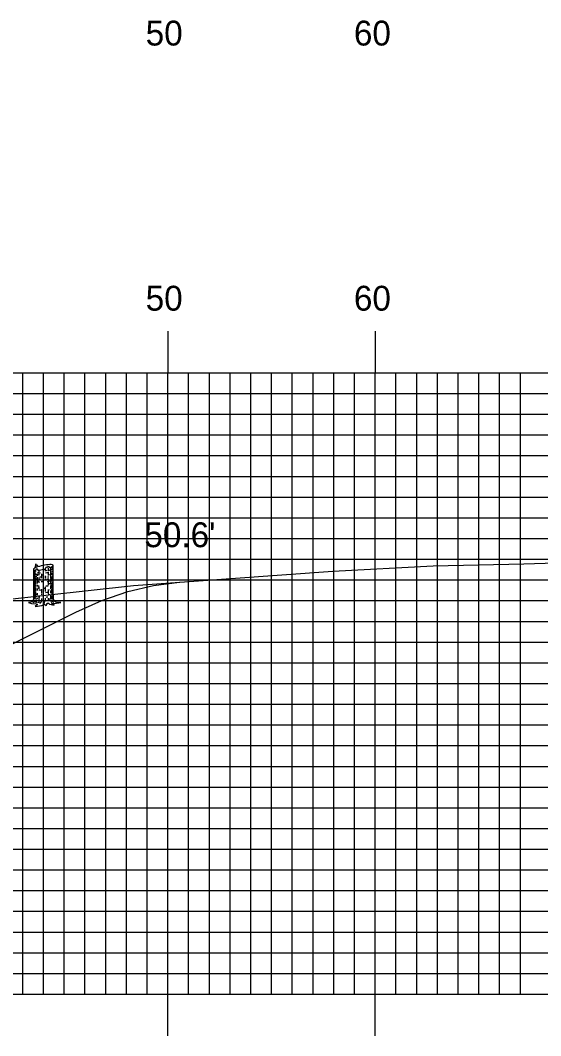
# Model space of a CAD drawing. Extents: x 1823966 to 1824309, y 442591 to 442811.
# Drawn here: x 1824174.71 to 1824199.8, y 442694.58 to 442743.61 of the extents above; entities that cross this region are included whole.
import ezdxf

# ---------------------------------------------------------------- set-up
doc = ezdxf.new("R2010")
doc.units = 0
for name, color, linetype in [('D_Roadway_Centerline', 7, 'Continuous'), ('D_Roadway_SlopeLines', 7, 'Continuous'), ('D_Text_Standard', 7, 'Continuous'), ('H_V ANNOTATION', 7, 'Continuous'), ('MAJOR', 7, 'Continuous'), ('MINOR', 7, 'Continuous'), ('S_Roadway_Centerline', 7, 'Continuous'), ('S_Trees_Decid_NonPay', 7, 'Continuous')]:
    doc.layers.add(name, color=color, linetype=linetype)

msp = doc.modelspace()

# ---------------------------------------------------------------- linework, layer by layer
at = {"layer": 'D_Roadway_Centerline'}
msp.add_lwpolyline([(1824101.648, 442710.342), (1824108.91, 442712.157), (1824111.822, 442712.885), (1824119.822, 442713.205), (1824131.822, 442713.445), (1824143.822, 442713.205), (1824151.822, 442712.885), (1824161.996, 442710.342), (1824165.996, 442709.342), (1824177.386, 442715.037), (1824178.636, 442715.596), (1824179.886, 442716.022), (1824181.136, 442716.317), (1824182.386, 442716.479)], dxfattribs=at)
at = {"layer": 'D_Roadway_SlopeLines'}
msp.add_lwpolyline([(1824165.996, 442709.342), (1824177.386, 442715.037), (1824178.636, 442715.596), (1824179.886, 442716.022), (1824181.136, 442716.317), (1824182.386, 442716.479)], dxfattribs=at)
at = {"layer": 'MAJOR'}
for p, q in [((1824181.822, 442728.592), (1824181.822, 442726.588)), ((1824191.822, 442728.592), (1824191.822, 442726.588)), ((1823991.822, 442726.588), (1824271.822, 442726.588)), ((1823991.822, 442726.588), (1824271.822, 442726.588)), ((1824181.822, 442696.588), (1824181.822, 442726.588)), ((1824191.822, 442696.588), (1824191.822, 442726.588)), ((1823991.822, 442721.588), (1824271.822, 442721.588)), ((1823991.822, 442716.588), (1824271.822, 442716.588)), ((1823991.822, 442711.588), (1824271.822, 442711.588)), ((1823991.822, 442706.588), (1824271.822, 442706.588)), ((1823991.822, 442701.588), (1824271.822, 442701.588)), ((1823991.822, 442696.588), (1824271.822, 442696.588)), ((1823991.822, 442696.588), (1824271.822, 442696.588)), ((1824181.822, 442694.584), (1824181.822, 442696.588)), ((1824191.822, 442694.584), (1824191.822, 442696.588))]:
    msp.add_line(p, q, dxfattribs=at)
at = {"layer": 'MINOR'}
for p, q in [((1824174.822, 442696.588), (1824174.822, 442726.588)), ((1824175.822, 442696.588), (1824175.822, 442726.588)), ((1824176.822, 442696.588), (1824176.822, 442726.588)), ((1824177.822, 442696.588), (1824177.822, 442726.588)), ((1824178.822, 442696.588), (1824178.822, 442726.588)), ((1824179.822, 442696.588), (1824179.822, 442726.588)), ((1824180.822, 442696.588), (1824180.822, 442726.588)), ((1824182.822, 442696.588), (1824182.822, 442726.588)), ((1824183.822, 442696.588), (1824183.822, 442726.588)), ((1824184.822, 442696.588), (1824184.822, 442726.588)), ((1824185.822, 442696.588), (1824185.822, 442726.588)), ((1824186.822, 442696.588), (1824186.822, 442726.588)), ((1824187.822, 442696.588), (1824187.822, 442726.588)), ((1824188.822, 442696.588), (1824188.822, 442726.588)), ((1824189.822, 442696.588), (1824189.822, 442726.588)), ((1824190.822, 442696.588), (1824190.822, 442726.588)), ((1824192.822, 442696.588), (1824192.822, 442726.588)), ((1824193.822, 442696.588), (1824193.822, 442726.588)), ((1824194.822, 442696.588), (1824194.822, 442726.588)), ((1824195.822, 442696.588), (1824195.822, 442726.588)), ((1824196.822, 442696.588), (1824196.822, 442726.588)), ((1824197.822, 442696.588), (1824197.822, 442726.588)), ((1824198.822, 442696.588), (1824198.822, 442726.588)), ((1823991.822, 442725.588), (1824271.822, 442725.588)), ((1823991.822, 442724.588), (1824271.822, 442724.588)), ((1823991.822, 442723.588), (1824271.822, 442723.588)), ((1823991.822, 442722.588), (1824271.822, 442722.588)), ((1823991.822, 442720.588), (1824271.822, 442720.588)), ((1823991.822, 442719.588), (1824271.822, 442719.588)), ((1823991.822, 442718.588), (1824271.822, 442718.588)), ((1823991.822, 442717.588), (1824271.822, 442717.588)), ((1823991.822, 442715.588), (1824271.822, 442715.588)), ((1823991.822, 442714.588), (1824271.822, 442714.588)), ((1823991.822, 442713.588), (1824271.822, 442713.588)), ((1823991.822, 442712.588), (1824271.822, 442712.588)), ((1823991.822, 442710.588), (1824271.822, 442710.588)), ((1823991.822, 442709.588), (1824271.822, 442709.588)), ((1823991.822, 442708.588), (1824271.822, 442708.588)), ((1823991.822, 442707.588), (1824271.822, 442707.588)), ((1823991.822, 442705.588), (1824271.822, 442705.588)), ((1823991.822, 442704.588), (1824271.822, 442704.588)), ((1823991.822, 442703.588), (1824271.822, 442703.588)), ((1823991.822, 442702.588), (1824271.822, 442702.588)), ((1823991.822, 442700.588), (1824271.822, 442700.588)), ((1823991.822, 442699.588), (1824271.822, 442699.588)), ((1823991.822, 442698.588), (1824271.822, 442698.588)), ((1823991.822, 442697.588), (1824271.822, 442697.588))]:
    msp.add_line(p, q, dxfattribs=at)
at = {"layer": 'S_Roadway_Centerline'}
msp.add_lwpolyline([(1824143.98, 442712.654), (1824145.907, 442712.678), (1824147.989, 442712.271), (1824148.362, 442712.203), (1824148.8, 442712.127), (1824152.854, 442711.284), (1824152.982, 442711.332), (1824155.841, 442711.355), (1824155.942, 442711.352), (1824156.136, 442711.464), (1824156.836, 442711.769), (1824157.71, 442712.162), (1824159.394, 442712.816), (1824164.55, 442714.059), (1824169.771, 442715.212), (1824170.867, 442715.316), (1824171.695, 442715.382), (1824180.171, 442716.318), (1824189.783, 442717.016), (1824194.617, 442717.262), (1824198.985, 442717.368), (1824210.288, 442717.724)], dxfattribs=at)
at = {"layer": 'S_Trees_Decid_NonPay'}
for p, q in [((1824176.046, 442717.161), (1824176.046, 442717.013)), ((1824176.164, 442717.144), (1824176.164, 442716.844)), ((1824176.233, 442717.231), (1824176.233, 442717.136)), ((1824175.374, 442716.988), (1824175.374, 442716.906)), ((1824175.374, 442716.836), (1824175.374, 442716.706)), ((1824175.374, 442716.684), (1824175.374, 442716.502)), ((1824175.401, 442717.058), (1824175.401, 442716.84)), ((1824175.401, 442716.771), (1824175.401, 442716.619)), ((1824175.444, 442717.053), (1824175.444, 442717.001)), ((1824175.444, 442716.898), (1824175.444, 442716.815)), ((1824175.444, 442716.78), (1824175.444, 442716.706)), ((1824175.444, 442716.679), (1824175.444, 442716.619)), ((1824175.515, 442716.879), (1824175.515, 442716.793)), ((1824175.515, 442716.722), (1824175.515, 442716.601)), ((1824175.601, 442717.063), (1824175.601, 442716.984)), ((1824175.601, 442716.898), (1824175.601, 442716.813)), ((1824175.601, 442716.702), (1824175.601, 442716.601)), ((1824175.719, 442716.879), (1824175.719, 442716.679)), ((1824175.899, 442717.115), (1824175.899, 442717.009)), ((1824175.899, 442716.78), (1824175.899, 442716.694)), ((1824175.899, 442716.659), (1824175.899, 442716.589)), ((1824176.046, 442716.965), (1824176.046, 442716.797)), ((1824176.164, 442716.815), (1824176.164, 442716.684)), ((1824176.164, 442716.65), (1824176.164, 442716.369)), ((1824176.233, 442716.91), (1824176.233, 442716.827)), ((1824176.233, 442716.758), (1824176.233, 442716.507)), ((1824175.374, 442716.455), (1824175.374, 442716.208)), ((1824175.374, 442716.189), (1824175.374, 442716.095)), ((1824175.401, 442716.514), (1824175.401, 442716.436)), ((1824175.401, 442716.409), (1824175.401, 442716.303)), ((1824175.401, 442716.268), (1824175.401, 442716.167)), ((1824175.444, 442716.566), (1824175.444, 442716.385)), ((1824175.444, 442716.354), (1824175.444, 442716.272)), ((1824175.444, 442716.218), (1824175.444, 442716.047)), ((1824175.515, 442716.526), (1824175.515, 442716.411)), ((1824175.515, 442716.35), (1824175.515, 442716.268)), ((1824175.515, 442716.181), (1824175.515, 442716.084)), ((1824175.601, 442716.516), (1824175.601, 442716.44)), ((1824175.601, 442716.255), (1824175.601, 442716.158)), ((1824175.899, 442716.255), (1824175.899, 442716.033)), ((1824176.046, 442716.49), (1824176.046, 442716.342)), ((1824176.164, 442716.299), (1824176.164, 442716.154)), ((1824176.233, 442716.424), (1824176.233, 442716.194)), ((1824175.372, 442716.041), (1824175.374, 442715.782)), ((1824175.374, 442715.743), (1824175.374, 442715.669)), ((1824175.401, 442716.141), (1824175.401, 442715.959)), ((1824175.401, 442715.856), (1824175.401, 442715.664)), ((1824175.444, 442716.014), (1824175.444, 442715.734)), ((1824175.444, 442715.682), (1824175.444, 442715.656)), ((1824175.515, 442715.955), (1824175.515, 442715.856)), ((1824175.515, 442715.726), (1824175.515, 442715.668)), ((1824175.601, 442715.833), (1824175.601, 442715.609)), ((1824175.719, 442716.142), (1824175.719, 442715.955)), ((1824175.719, 442715.924), (1824175.719, 442715.871)), ((1824175.719, 442715.695), (1824175.719, 442715.604)), ((1824175.899, 442715.699), (1824175.899, 442715.633)), ((1824176.046, 442716.072), (1824176.046, 442715.919)), ((1824176.046, 442715.707), (1824176.046, 442715.629)), ((1824176.164, 442716.084), (1824176.164, 442715.942)), ((1824176.164, 442715.841), (1824176.164, 442715.66)), ((1824176.233, 442716.123), (1824176.233, 442715.963)), ((1824176.233, 442715.946), (1824176.233, 442715.841)), ((1824176.233, 442715.804), (1824176.233, 442715.68)), ((1824175.321, 442715.495), (1824175.389, 442715.526)), ((1824175.403, 442715.617), (1824175.368, 442715.566)), ((1824175.859, 442715.413), (1824175.893, 442715.559)), ((1824176.165, 442715.6), (1824176.206, 442715.504))]:
    msp.add_line(p, q, dxfattribs=at)
for points in [[(1824175.333, 442717.095), (1824175.333, 442715.683), (1824175.311, 442715.535), (1824175.107, 442715.491), (1824175.247, 442715.456), (1824175.466, 442715.438), (1824175.535, 442715.394), (1824175.414, 442715.306), (1824175.745, 442715.349), (1824175.859, 442715.413), (1824175.951, 442715.353), (1824176.007, 442715.432), (1824175.998, 442715.469), (1824176.06, 442715.47), (1824176.112, 442715.413), (1824176.344, 442715.362), (1824176.217, 442715.45), (1824176.349, 442715.452), (1824176.657, 442715.49), (1824176.418, 442715.52), (1824176.34, 442715.578), (1824176.302, 442715.699), (1824176.284, 442716.053), (1824176.284, 442717.287)], [(1824175.428, 442717.176), (1824175.432, 442717.27), (1824175.447, 442717.243), (1824175.447, 442717.365), (1824175.468, 442717.301), (1824175.482, 442717.334), (1824175.498, 442717.278), (1824175.515, 442717.295), (1824175.533, 442717.287), (1824175.552, 442717.22)], [(1824175.45, 442717.052), (1824175.468, 442717.114), (1824175.49, 442717.102), (1824175.521, 442717.136), (1824175.554, 442717.058)], [(1824175.92, 442717.121), (1824175.929, 442717.188), (1824175.953, 442717.192), (1824175.962, 442717.227), (1824175.992, 442717.213), (1824176.007, 442717.227), (1824176.031, 442717.204), (1824176.054, 442717.213), (1824176.067, 442717.262), (1824176.075, 442717.219), (1824176.105, 442717.227), (1824176.109, 442717.176)], [(1824175.372, 442715.543), (1824175.451, 442715.526), (1824175.468, 442715.483)], [(1824175.451, 442715.526), (1824175.494, 442715.561), (1824175.502, 442715.609)], [(1824175.599, 442715.561), (1824175.593, 442715.491), (1824175.529, 442715.479)], [(1824175.71, 442715.555), (1824175.71, 442715.518), (1824175.659, 442715.488), (1824175.642, 442715.438)], [(1824176.235, 442715.638), (1824176.244, 442715.561), (1824176.322, 442715.512)]]:
    msp.add_lwpolyline(points, dxfattribs=at)
for centre, radius, start, end in [((1824175.567, 442716.886), 0.322, 109.7098, 131.8277), ((1824176.304, 442714.828), 2.507, 101.8277, 109.7098), ((1824176.304, 442714.828), 2.507, 93.9457, 101.8277), ((1824175.314, 442719.554), 2.507, 288.4719, 289.7098), ((1824176.153, 442717.008), 0.322, 71.8277, 93.9457), ((1824176.051, 442717.496), 0.322, 289.7098, 311.8277), ((1824176.224, 442717.225), 0.0935, 60.604, 71.8277), ((1824176.203, 442717.326), 0.0935, 311.8277, 323.0514), ((1824176.254, 442717.278), 0.0336, 41.8277, 60.604), ((1824176.251, 442717.29), 0.0336, 323.0514, 341.8277), ((1824176.261, 442717.284), 0.0237, 27.8832, 41.8277), ((1824176.266, 442717.287), 0.0179, 11.8277, 27.8832), ((1824176.26, 442717.141), 0.0252, 330, 343.9485), ((1824176.26, 442717.287), 0.0237, 341.8277, 355.7722), ((1824176.266, 442717.287), 0.0179, 355.7722, 11.8277), ((1824176.266, 442717.139), 0.0191, 0, 16.0515), ((1824176.266, 442717.139), 0.0191, 343.9485, 0), ((1824175.357, 442717.095), 0.0237, 161.8277, 175.7722), ((1824175.351, 442717.095), 0.0179, 175.7722, 191.8277), ((1824175.351, 442717.095), 0.0179, 191.8277, 207.8832), ((1824175.353, 442717.026), 0.0191, 173.8872, 180), ((1824175.353, 442717.026), 0.0191, 180, 196.0515), ((1824175.353, 442716.925), 0.0191, 173.8872, 180), ((1824175.353, 442716.925), 0.0191, 180, 196.0515), ((1824175.353, 442716.822), 0.0191, 173.8872, 180), ((1824175.353, 442716.822), 0.0191, 180, 196.0515), ((1824175.353, 442716.717), 0.0191, 173.8872, 180), ((1824175.353, 442716.717), 0.0191, 180, 196.0515), ((1824175.366, 442717.092), 0.0336, 143.0514, 161.8277), ((1824175.356, 442717.098), 0.0237, 207.8832, 221.8277), ((1824175.359, 442717.028), 0.0252, 196.0515, 210), ((1824175.359, 442716.927), 0.0252, 196.0515, 210), ((1824175.359, 442716.719), 0.0252, 196.0515, 210), ((1824175.368, 442717.033), 0.0356, 210, 228.7494), ((1824175.368, 442716.932), 0.0356, 210, 228.7494), ((1824175.368, 442716.724), 0.0356, 210, 228.7494), ((1824175.364, 442717.105), 0.0336, 221.8277, 240.604), ((1824175.414, 442717.056), 0.0935, 131.8277, 143.0514), ((1824175.409, 442717.08), 0.0984, 228.7494, 240), ((1824175.409, 442716.979), 0.0984, 228.7494, 240), ((1824175.409, 442716.771), 0.0984, 228.7494, 240), ((1824175.393, 442717.157), 0.0935, 240.604, 251.8277), ((1824175.523, 442717.277), 0.326, 240, 248.0494), ((1824175.523, 442717.177), 0.326, 240, 248.0494), ((1824175.523, 442716.969), 0.326, 240, 248.0494), ((1824175.464, 442717.374), 0.322, 251.8277, 267.5521), ((1824175.523, 442717.074), 0.326, 255.9618, 261.8968), ((1824175.523, 442716.969), 0.326, 255.9618, 261.8968), ((1824175.523, 442717.177), 0.326, 260.9146, 261.8968), ((1824175.81, 442719.187), 2.356, 261.8968, 264.9353), ((1824175.81, 442719.084), 2.356, 261.8968, 262.6162), ((1824175.81, 442718.979), 2.356, 261.8968, 262.8132), ((1824175.81, 442719.288), 2.356, 263.2266, 266.8519), ((1824175.314, 442719.554), 2.507, 275.4987, 281.8277), ((1824175.81, 442719.084), 2.356, 266.0259, 267.8019), ((1824175.81, 442719.187), 2.356, 267.8019, 269.1881), ((1824175.314, 442719.554), 2.507, 281.8277, 284.0013), ((1824175.81, 442719.401), 2.356, 272.1614, 274.76), ((1824175.81, 442719.084), 2.356, 272.1614, 273.4964), ((1824175.81, 442719.288), 2.356, 272.6327, 275.758), ((1824175.81, 442719.084), 2.356, 275.0054, 276.6587), ((1824175.81, 442719.401), 2.356, 276.7201, 278.1032), ((1824175.81, 442719.187), 2.356, 277.4481, 278.1032), ((1824176.096, 442717.391), 0.326, 278.1032, 282.1964), ((1824176.096, 442717.177), 0.326, 278.1032, 289.5833), ((1824176.096, 442717.277), 0.326, 282.1964, 299.0901), ((1824176.096, 442717.074), 0.326, 282.1964, 288.3169), ((1824176.096, 442716.969), 0.326, 282.1964, 294.8455), ((1824176.096, 442717.391), 0.326, 291.6757, 300), ((1824176.096, 442717.177), 0.326, 296.4281, 300), ((1824176.096, 442717.074), 0.326, 296.757, 300), ((1824176.21, 442717.194), 0.0984, 300, 311.2506), ((1824176.21, 442716.979), 0.0984, 300, 311.2506), ((1824176.21, 442716.876), 0.0984, 300, 311.2506), ((1824176.251, 442717.146), 0.0356, 311.2506, 330), ((1824176.251, 442716.932), 0.0356, 311.2506, 330), ((1824176.251, 442716.829), 0.0356, 311.2506, 330), ((1824176.26, 442716.927), 0.0252, 330, 343.9485), ((1824176.26, 442716.824), 0.0252, 330, 343.9485), ((1824176.266, 442716.925), 0.0191, 0, 16.0515), ((1824176.266, 442716.925), 0.0191, 343.9485, 0), ((1824176.266, 442716.822), 0.0191, 0, 16.0515), ((1824176.266, 442716.822), 0.0191, 343.9485, 0), ((1824175.352, 442716.488), 0.0191, 173.8872, 180), ((1824175.352, 442716.488), 0.0191, 180, 196.0515), ((1824175.353, 442716.602), 0.0191, 173.8872, 180), ((1824175.353, 442716.602), 0.0191, 180, 196.0515), ((1824175.358, 442716.49), 0.0252, 196.0515, 210), ((1824175.353, 442716.283), 0.0191, 173.8872, 180), ((1824175.353, 442716.283), 0.0191, 180, 196.0515), ((1824175.353, 442716.192), 0.0191, 173.8872, 180), ((1824175.359, 442716.604), 0.0252, 196.0515, 210), ((1824175.359, 442716.285), 0.0252, 196.0515, 210), ((1824175.367, 442716.495), 0.0356, 210, 228.7494), ((1824175.356, 442716.388), 0.0191, 173.8872, 180), ((1824175.356, 442716.388), 0.0191, 180, 196.0515), ((1824175.368, 442716.609), 0.0356, 210, 228.7494), ((1824175.361, 442716.389), 0.0252, 196.0515, 210), ((1824175.368, 442716.29), 0.0356, 210, 228.7494), ((1824175.37, 442716.395), 0.0356, 210, 228.7494), ((1824175.409, 442716.542), 0.0984, 228.7494, 240), ((1824175.409, 442716.656), 0.0984, 228.7494, 240), ((1824175.409, 442716.337), 0.0984, 228.7494, 240), ((1824175.412, 442716.442), 0.0984, 228.7494, 240), ((1824175.523, 442716.854), 0.326, 240, 255.9618), ((1824175.523, 442716.739), 0.326, 240, 242.9942), ((1824175.523, 442716.534), 0.326, 240, 242.8475), ((1824175.526, 442716.639), 0.326, 240, 247.5951), ((1824175.523, 442716.739), 0.326, 248.1902, 256.0964), ((1824175.523, 442716.534), 0.326, 248.0494, 255.9618), ((1824175.81, 442718.864), 2.356, 262.8132, 264.9353), ((1824175.812, 442718.649), 2.356, 262.7545, 265.0266), ((1824175.81, 442718.544), 2.356, 263.572, 264.9353), ((1824175.81, 442718.979), 2.356, 264.9353, 266.9933), ((1824175.81, 442718.864), 2.356, 267.586, 270), ((1824175.81, 442718.864), 2.356, 270, 270.4422), ((1824175.81, 442718.544), 2.356, 270.9946, 272.1614), ((1824175.812, 442718.649), 2.356, 273.1471, 275.6557), ((1824175.81, 442718.979), 2.356, 274.3638, 276.7318), ((1824175.81, 442718.864), 2.356, 275.2089, 277.3412), ((1824175.809, 442718.749), 2.356, 277.1385, 278.1032), ((1824176.095, 442716.739), 0.326, 278.1032, 282.3301), ((1824176.098, 442716.639), 0.326, 283.0921, 300), ((1824176.096, 442716.444), 0.326, 286.0817, 298.061), ((1824176.095, 442716.739), 0.326, 292.1344, 300), ((1824176.096, 442716.854), 0.326, 294.8455, 300), ((1824176.096, 442716.534), 0.326, 294.8455, 300), ((1824176.209, 442716.542), 0.0984, 300, 311.2506), ((1824176.21, 442716.656), 0.0984, 300, 311.2506), ((1824176.21, 442716.337), 0.0984, 300, 311.2506), ((1824176.251, 442716.609), 0.0356, 311.2506, 330), ((1824176.25, 442716.495), 0.0356, 311.2506, 330), ((1824176.251, 442716.29), 0.0356, 311.2506, 330), ((1824176.259, 442716.49), 0.0252, 330, 343.9485), ((1824176.26, 442716.604), 0.0252, 330, 343.9485), ((1824176.26, 442716.285), 0.0252, 330, 343.9485), ((1824176.265, 442716.488), 0.0191, 0, 16.0515), ((1824176.265, 442716.488), 0.0191, 343.9485, 0), ((1824176.266, 442716.602), 0.0191, 0, 16.0515), ((1824176.266, 442716.602), 0.0191, 343.9485, 0), ((1824176.266, 442716.283), 0.0191, 0, 16.0515), ((1824176.266, 442716.283), 0.0191, 343.9485, 0), ((1824176.268, 442716.388), 0.0191, 0, 16.0515), ((1824175.357, 442715.964), 0.0191, 173.8872, 180), ((1824175.357, 442715.964), 0.0191, 180, 196.0515), ((1824175.363, 442715.966), 0.0252, 196.0515, 210), ((1824175.372, 442715.971), 0.0356, 210, 228.7494), ((1824175.368, 442715.743), 0.0191, 173.8872, 180), ((1824175.368, 442715.743), 0.0191, 180, 196.0515), ((1824175.414, 442716.018), 0.0984, 228.7494, 240), ((1824175.373, 442715.745), 0.0252, 196.0515, 210), ((1824175.383, 442715.75), 0.0356, 210, 228.7494), ((1824175.424, 442715.797), 0.0984, 228.7494, 240), ((1824175.532, 442716.105), 0.326, 240, 246.3456), ((1824175.523, 442716.33), 0.326, 248.0494, 255.9618), ((1824175.538, 442715.994), 0.326, 245.2906, 261.8968), ((1824175.527, 442716.215), 0.326, 255.2259, 261.8968), ((1824175.814, 442718.225), 2.356, 261.8968, 262.7137), ((1824175.824, 442718.004), 2.356, 261.8968, 262.4597), ((1824175.81, 442718.454), 2.356, 264.7274, 267.8019), ((1824175.818, 442718.115), 2.356, 264.7171, 265.8136), ((1824175.81, 442718.34), 2.356, 272.531, 275.758), ((1824175.818, 442718.115), 2.356, 273.1842, 275.0911), ((1824175.81, 442718.454), 2.356, 275.5135, 277.4157), ((1824175.814, 442718.225), 2.356, 275.5148, 277.7774), ((1824175.824, 442718.004), 2.356, 276.4667, 278.1032), ((1824176.11, 442715.994), 0.326, 278.1032, 279.6166), ((1824176.1, 442716.215), 0.326, 294.0625, 300), ((1824176.11, 442715.994), 0.326, 292.0839, 300), ((1824176.105, 442716.105), 0.326, 298.0903, 300), ((1824176.214, 442716.018), 0.0984, 300, 311.2506), ((1824176.218, 442715.907), 0.0984, 300, 311.2506), ((1824176.224, 442715.797), 0.0984, 300, 311.2506), ((1824176.255, 442715.971), 0.0356, 311.2506, 330), ((1824176.26, 442715.86), 0.0356, 311.2506, 330), ((1824176.264, 442715.966), 0.0252, 330, 343.9485), ((1824176.27, 442715.964), 0.0191, 0, 16.0515), ((1824176.27, 442715.964), 0.0191, 343.9485, 0), ((1824176.265, 442715.75), 0.0356, 311.2506, 330), ((1824176.269, 442715.855), 0.0252, 330, 343.9485), ((1824176.275, 442715.853), 0.0191, 0, 16.0515), ((1824176.275, 442715.853), 0.0191, 343.9485, 0), ((1824176.274, 442715.745), 0.0252, 330, 343.9485), ((1824176.28, 442715.743), 0.0191, 0, 16.0515), ((1824176.28, 442715.743), 0.0191, 343.9485, 0), ((1824175.824, 442718.004), 2.356, 264.5833, 265.4449)]:
    msp.add_arc(centre, radius, start, end, dxfattribs=at)

# ---------------------------------------------------------------- texts
at = {"layer": 'D_Text_Standard'}
msp.add_text("50.6'", height=1.2, dxfattribs=at).set_placement((1824180.687, 442718.168))
at = {"layer": 'H_V ANNOTATION'}
for s, p in [('50', (1824180.751, 442742.388)), ('60', (1824190.794, 442742.388)), ('50', (1824180.751, 442729.588)), ('60', (1824190.794, 442729.588))]:
    msp.add_text(s, height=1.2, dxfattribs=at).set_placement(p)

doc.saveas('drawing.dxf')
